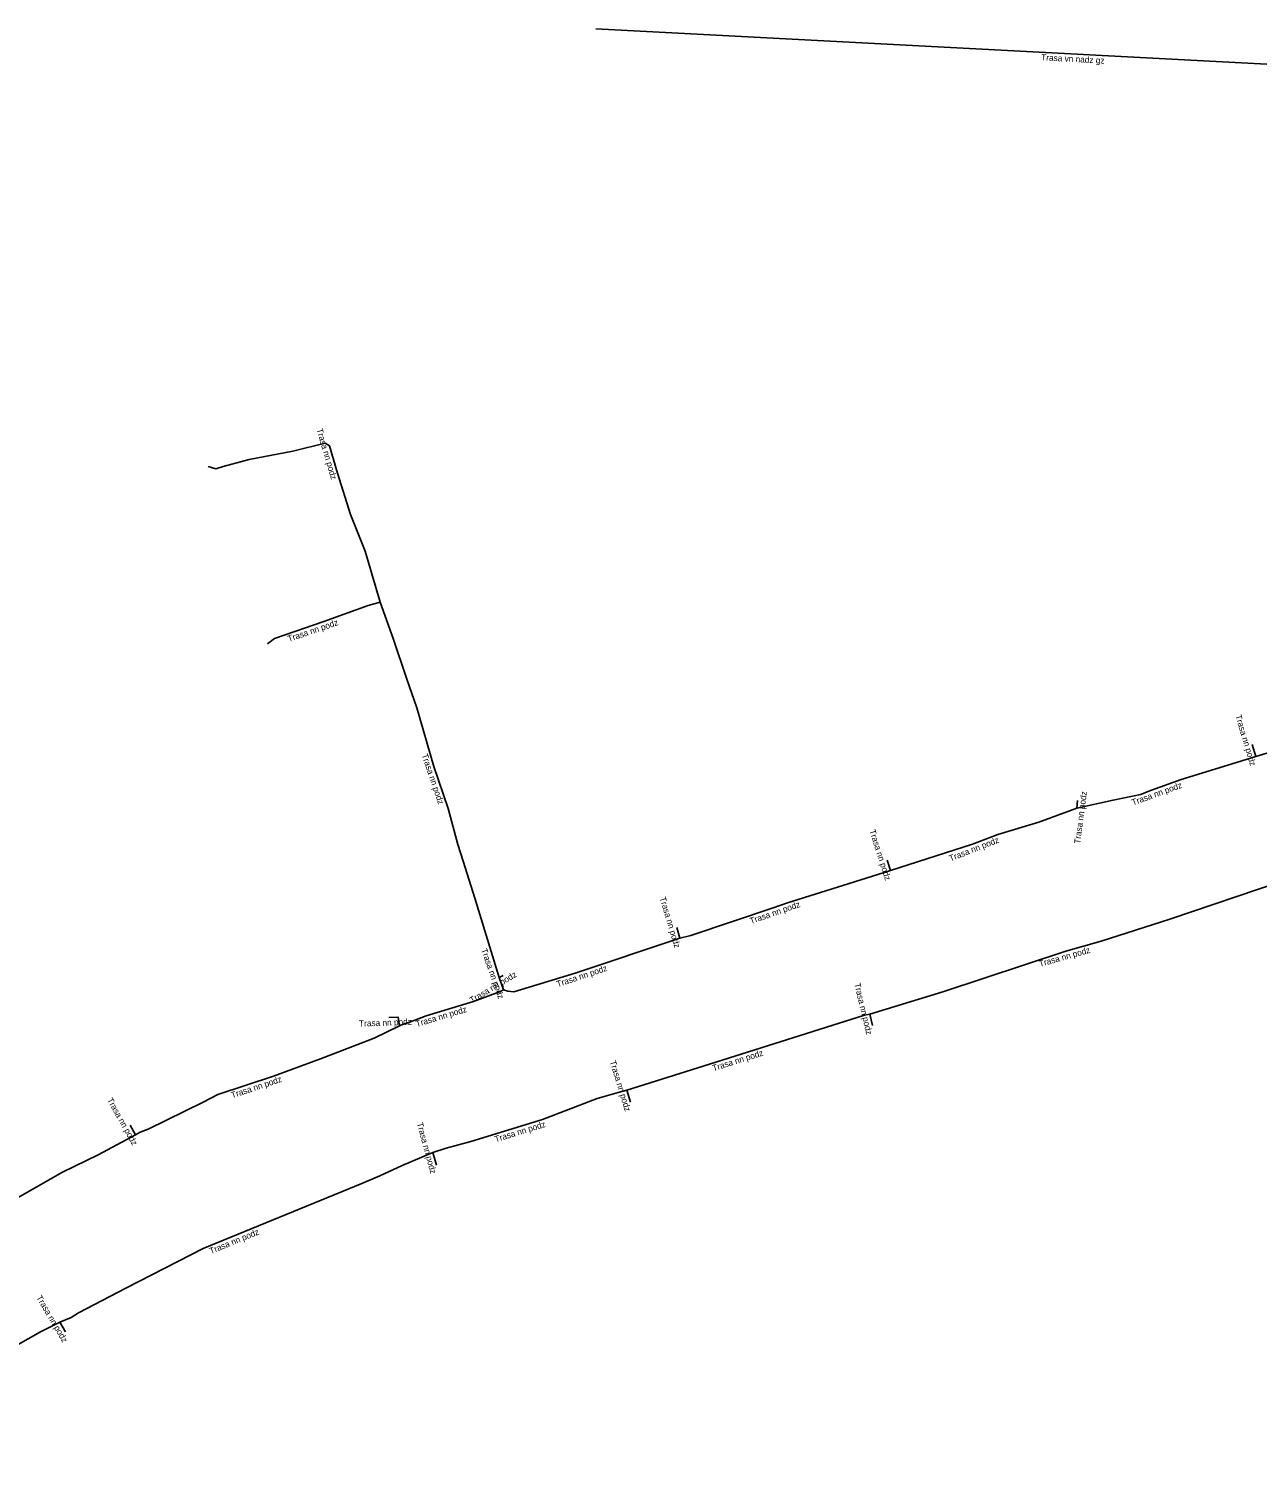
# Model space of a CAD drawing. Extents: x -756855 to -756032, y -1046964 to -1046550.
# Drawn here: x -756576.6 to -756477.2, y -1046666.5 to -1046550.1 of the extents above; entities that cross this region are included whole.
import ezdxf

# ---------------------------------------------------------------- set-up
doc = ezdxf.new("R2010")
doc.units = 0
for name, color, linetype in [('Popiskový text - Ostatní atributy Trasy', 7, 'Continuous'), ('Spojnice NN', 7, 'Continuous'), ('Spojnice VN', 7, 'Continuous')]:
    doc.layers.add(name, color=color, linetype=linetype)

msp = doc.modelspace()

# ---------------------------------------------------------------- linework, layer by layer
at = {"layer": 'Spojnice NN'}
for points in [[(-756548.2, -1046596.46), (-756549.41, -1046592.32), (-756550.58, -1046589.37), (-756551.64, -1046586.02), (-756552.29, -1046583.8), (-756552.64, -1046583.6), (-756555.25, -1046584.24), (-756558.79, -1046584.92), (-756560.89, -1046585.48), (-756561.48, -1046585.66), (-756562.11, -1046585.48)], [(-756548.2, -1046596.46), (-756549.15, -1046596.74), (-756552.75, -1046598.03), (-756556.73, -1046599.39), (-756557.32, -1046599.84)], [(-756538.55, -1046626.84), (-756538.7, -1046626.39), (-756540.53, -1046620.41), (-756541.48, -1046617.43), (-756541.9, -1046616.08), (-756542.7, -1046613.15), (-756543.84, -1046609.76), (-756545.22, -1046605), (-756546.07, -1046602.61), (-756547.14, -1046599.39), (-756548.2, -1046596.46)], [(-756477.33, -1046608.96), (-756475.82, -1046608.49), (-756472.85, -1046607.49), (-756471.44, -1046606.96), (-756463.41, -1046604.4)], [(-756477.33, -1046608.96), (-756477.62, -1046607.99)], [(-756491.83, -1046613.13), (-756488.89, -1046612.47), (-756486.66, -1046612.03), (-756485.77, -1046611.68), (-756483.38, -1046610.81), (-756479.6, -1046609.65), (-756477.33, -1046608.96)], [(-756491.83, -1046613.13), (-756491.75, -1046612.52)], [(-756506.9, -1046618.18), (-756500.25, -1046616.05), (-756498.21, -1046615.25), (-756494.88, -1046614.25), (-756491.83, -1046613.13)], [(-756506.9, -1046618.18), (-756507.17, -1046617.33)], [(-756523.93, -1046623.65), (-756523.05, -1046623.43), (-756516.39, -1046621.19), (-756515.24, -1046620.79), (-756510.75, -1046619.38), (-756506.9, -1046618.18)], [(-756508.58, -1046629.79), (-756502.65, -1046628), (-756492.7, -1046624.71), (-756489.84, -1046623.9), (-756484.29, -1046622.11), (-756475.36, -1046619.1)], [(-756523.93, -1046623.65), (-756524.19, -1046622.78)], [(-756538.2, -1046627.83), (-756537.85, -1046627.95), (-756537.37, -1046628), (-756532.41, -1046626.47), (-756523.93, -1046623.65)], [(-756538.25, -1046626.66), (-756538.55, -1046626.84)], [(-756538.2, -1046627.83), (-756538.55, -1046626.84)], [(-756546.63, -1046630.74), (-756546.39, -1046630.64), (-756545.74, -1046630.41), (-756544.47, -1046629.93), (-756540.64, -1046628.78), (-756538.54, -1046628), (-756538.2, -1046627.83)], [(-756547.5, -1046630.07), (-756546.74, -1046630.04), (-756546.63, -1046630.74)], [(-756528.23, -1046635.96), (-756521.55, -1046633.84), (-756509.01, -1046629.89), (-756508.58, -1046629.79)], [(-756508.58, -1046629.79), (-756508.36, -1046630.71)], [(-756546.63, -1046630.74), (-756548.67, -1046631.74), (-756553.02, -1046633.4), (-756556.82, -1046634.81), (-756561.32, -1046636.31), (-756562.52, -1046636.93), (-756566.96, -1046639.1), (-756567.61, -1046639.36), (-756567.99, -1046639.56)], [(-756543.92, -1046640.98), (-756542.85, -1046640.65), (-756540.86, -1046640.11), (-756535.06, -1046638.32), (-756530.64, -1046636.61), (-756528.92, -1046636.13), (-756528.23, -1046635.96)], [(-756528.23, -1046635.96), (-756527.93, -1046636.93)], [(-756567.99, -1046639.56), (-756571.01, -1046641.17), (-756573.89, -1046642.58), (-756577.74, -1046644.77), (-756582.77, -1046647.38), (-756585.17, -1046648.81), (-756589.61, -1046651.58)], [(-756567.99, -1046639.56), (-756568.42, -1046638.79)], [(-756574.11, -1046654.73), (-756573.19, -1046654.35), (-756572.61, -1046653.96), (-756568.76, -1046651.97), (-756562.51, -1046648.77), (-756549.68, -1046643.51), (-756548.23, -1046642.88), (-756546.42, -1046642.04), (-756543.92, -1046640.98)], [(-756543.92, -1046640.98), (-756543.64, -1046642.02)], [(-756592.43, -1046666.46), (-756592.21, -1046666.22), (-756590.08, -1046664.69), (-756589.54, -1046664.28), (-756587.73, -1046663), (-756586.42, -1046662.11), (-756582.76, -1046659.56), (-756582.49, -1046659.37), (-756575.69, -1046655.5), (-756574.11, -1046654.73)], [(-756574.11, -1046654.73), (-756573.66, -1046655.5)]]:
    msp.add_lwpolyline(points, dxfattribs=at)
at = {"layer": 'Spojnice VN'}
msp.add_lwpolyline([(-756530.75, -1046550.06), (-756450.83, -1046554.28)], dxfattribs=at)

# ---------------------------------------------------------------- texts
at = {"layer": 'Popiskový text - Ostatní atributy Trasy'}
for s, rotation, p in [('Trasa vn nadz gz', 356.9774, (-756494.71, -1046552.61)), ('Trasa nn podz', 286.3197, (-756553.35, -1046582.48)), ('Trasa nn podz', 18.8657, (-756555.58, -1046599.68)), ('Trasa nn podz', 286.645, (-756479, -1046605.65)), ('Trasa nn podz', 288.5869, (-756544.84, -1046608.82)), ('Trasa nn podz', 20.0024, (-756487.27, -1046612.92)), ('Trasa nn podz', 82.5284, (-756491.55, -1046616.03)), ('Trasa nn podz', 287.6223, (-756508.61, -1046614.95)), ('Trasa nn podz', 21.413, (-756502.04, -1046617.45)), ('Trasa nn podz', 286.6388, (-756525.58, -1046620.39)), ('Trasa nn podz', 19.179, (-756518.19, -1046622.51)), ('Trasa nn podz', 289.4703, (-756540.04, -1046624.58)), ('Trasa nn podz', 15.813, (-756494.8, -1046625.98)), ('Trasa nn podz', 30.9638, (-756540.76, -1046628.93)), ('Trasa nn podz', 18.3944, (-756533.82, -1046627.62)), ('Trasa nn podz', 283.3869, (-756509.83, -1046627.34)), ('Trasa nn podz', 16.713, (-756545.23, -1046630.84)), ('Trasa nn podz', 2.2605, (-756549.89, -1046630.81)), ('Trasa nn podz', 287.0117, (-756529.62, -1046633.63)), ('Trasa nn podz', 17.484, (-756521.22, -1046634.42)), ('Trasa nn podz', 18.4349, (-756560.16, -1046636.61)), ('Trasa nn podz', 299.1808, (-756570.31, -1046636.74)), ('Trasa nn podz', 285.1991, (-756545.23, -1046638.63)), ('Trasa nn podz', 17.1513, (-756538.84, -1046640.17)), ('Trasa nn podz', 22.2925, (-756561.89, -1046649.22)), ('Trasa nn podz', 300.4039, (-756576.04, -1046652.73))]:
    msp.add_text(s, height=0.5, rotation=rotation, dxfattribs=at).set_placement(p)

doc.saveas('drawing.dxf')
